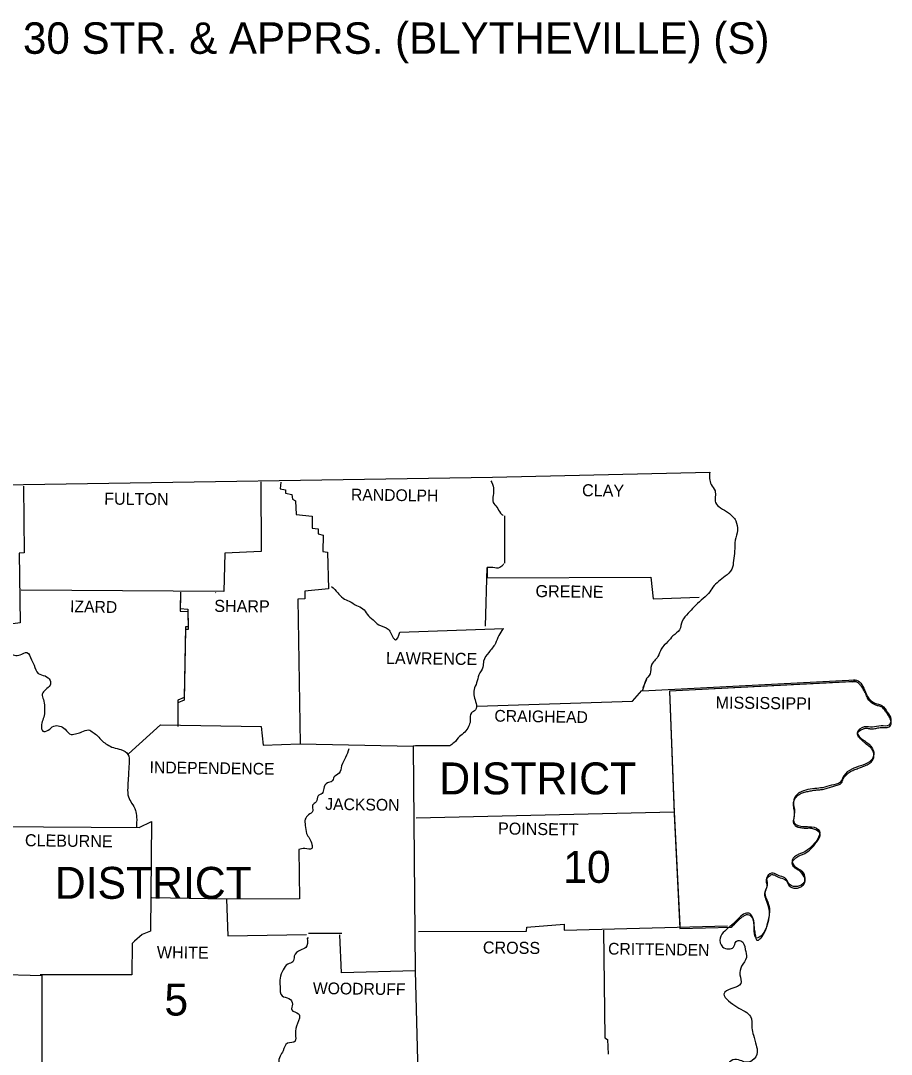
# Model space of a CAD drawing. Extents: x 171 to 3403, y 68 to 2102.
# Drawn here: x 2999.8 to 3303.9, y 1673 to 2034.2 of the extents above; entities that cross this region are included whole.
import ezdxf

# ---------------------------------------------------------------- set-up
doc = ezdxf.new("R2010")
doc.units = 0
for name, color, linetype in [('1', 7, 'Continuous'), ('2', 7, 'Continuous'), ('3', 7, 'Continuous'), ('R_Border', 7, 'Continuous'), ('S_MISC_BOUNDARY', 7, 'Continuous')]:
    doc.layers.add(name, color=color, linetype=linetype)

msp = doc.modelspace()

# ---------------------------------------------------------------- linework, layer by layer
at = {"layer": '1'}
for p, q in [((3216.98, 1800), (3218.15, 1803.62)), ((3217.27, 1801.17), (3218.45, 1804.01)), ((3100.35, 1715.27), (3112, 1715.27))]:
    msp.add_line(p, q, dxfattribs=at)
for points in [[(2703.71, 1871.91), (2861.92, 1871.81), (3000.75, 1872.1), (3164.54, 1874.65), (3240.46, 1876.41)], [(3000.75, 1871.52), (3000.95, 1848.23), (2999.28, 1848.13), (2999.58, 1823.77), (2992.73, 1822.79), (2993.32, 1816.24), (2995.66, 1813.2), (2995.47, 1805.48), (2982.16, 1804.99), (2981.67, 1793.05), (2969.54, 1792.66), (2968.95, 1778.18), (2969.64, 1777), (2969.93, 1753.91), (2990.87, 1752.54), (2990.58, 1700.98), (3007.21, 1700.49), (3007.21, 1648.05), (2994.1, 1647.07), (2993.12, 1635.53), (2971.11, 1635.43)], [(3083.62, 1872.99), (3083.82, 1848.72), (3071.1, 1848.04), (3070.71, 1834.73), (2999.97, 1835.12)], [(3090.67, 1872.89), (3090.37, 1870.54), (3092.33, 1870.25), (3092.23, 1869.07), (3094.48, 1868.58), (3094.68, 1867.02), (3095.75, 1866.33), (3096.05, 1861.64), (3101.63, 1861.05), (3101.63, 1856.84), (3103.68, 1856.55), (3103.68, 1854.88), (3105.44, 1854.4), (3105.34, 1848.72), (3106.91, 1848.43), (3107.3, 1835.61), (3098.98, 1834.83), (3099.08, 1832.09), (3096.54, 1831.99), (3097.42, 1781.5), (3136.85, 1780.62), (3137.53, 1702.16), (3111.8, 1701.47), (3111.31, 1714.68)], [(3168.84, 1861.15), (3168.84, 1844.61)], [(3162.19, 1822.6), (3162.68, 1843.05), (3162.68, 1839.43), (3219.91, 1839.72), (3220.7, 1832.09), (3236.84, 1832.67)], [(3055.64, 1834.44), (3055.44, 1828.76), (3058.18, 1828.57), (3058.28, 1822.3), (3057.3, 1822.3), (3056.91, 1797.65), (3054.66, 1796.67), (3054.66, 1788.45)], [(3055.64, 1833.56), (3055.44, 1827.88), (3058.18, 1827.69), (3058.28, 1821.42), (3057.3, 1821.42), (3056.91, 1796.77), (3054.66, 1795.79), (3054.66, 1787.57)], [(3067.87, 1834.24), (3067.97, 1834.34)], [(3132.25, 1820.44), (3168.55, 1821.72)], [(3216.98, 1800), (3291.24, 1803.81)], [(3159.25, 1794.61), (3213.55, 1796.38), (3216.78, 1800.09)], [(3226.37, 1799.9), (3228.04, 1757.53), (3229.99, 1718.1)], [(3037.44, 1777.98), (3048.6, 1788.06), (3083.82, 1787.57), (3084.5, 1781.02), (3097.32, 1781.5)], [(3149.67, 1780.82), (3137.73, 1780.82), (3136.85, 1780.62)], [(3228.04, 1757.53), (3137.92, 1755.48)], [(2990.87, 1752.54), (3041.16, 1752.25), (3045.46, 1754.3), (3045.17, 1716.05), (3042.24, 1714.78), (3039.59, 1712.53), (3038.71, 1711.65), (3038.62, 1700.69), (3006.62, 1700.69)], [(3096.93, 1744.52), (3097.12, 1727.3), (3071.69, 1727.2), (3045.56, 1727.69)], [(3071.69, 1727.2), (3072.08, 1714.39), (3099.57, 1714.87)], [(3138.71, 1715.85), (3176.47, 1716.05), (3176.57, 1717.42), (3189.68, 1718.4), (3189.68, 1716.34), (3246.63, 1717.91)], [(3203.38, 1716.34), (3203.87, 1678.67), (3204.75, 1678.09), (3205.04, 1673)], [(3100.35, 1713.6), (3099.86, 1713.51)], [(3137.53, 1702.16), (3139, 1648.54), (3115.71, 1648.44), (3115.62, 1646.29), (3108.87, 1645.9), (3108.28, 1634.74), (3100.06, 1634.74)]]:
    msp.add_lwpolyline(points, dxfattribs=at)
for points in [[(3240.46, 1876.41), (3240.95, 1872.1), (3242.32, 1869.85), (3242.52, 1865.75), (3244.18, 1863.98), (3247.02, 1862.22), (3249.56, 1859.39), (3250.15, 1856.06), (3249.36, 1852.63), (3249.17, 1848.82), (3248.78, 1845.49), (3248.19, 1842.46), (3245.84, 1840.01), (3243.59, 1838.25), (3241.54, 1836.2), (3240.07, 1834.04), (3237.53, 1831.7), (3234.98, 1829.25), (3232.93, 1827.1), (3230.87, 1824.36), (3229.89, 1821.33), (3227.64, 1819.17), (3225.88, 1817.22), (3223.53, 1814.57), (3222.36, 1811.93), (3220.11, 1808.9), (3219.62, 1805.96), (3218.15, 1803.62), (3218.06, 1803.22)], [(3164.05, 1873.38), (3164.93, 1870.93), (3164.83, 1868.29), (3164.83, 1865.84), (3166.1, 1864.18), (3167.37, 1862.13), (3168.35, 1861.24)], [(3168.45, 1844.32), (3167.18, 1843.05), (3164.73, 1843.05), (3162.68, 1843.05)], [(3108.38, 1836.49), (3110.53, 1834.24), (3112.39, 1832.38), (3114.54, 1831.31), (3117.08, 1829.84), (3119.33, 1828.66), (3120.8, 1826.8), (3122.86, 1824.75), (3124.91, 1823.09), (3128.14, 1821.52), (3129.22, 1819.86), (3130.68, 1817.8), (3132.25, 1820.44)], [(3168.25, 1821.62), (3166.79, 1819.27), (3165.61, 1816.53), (3163.26, 1813.4), (3161.5, 1810.37), (3161.21, 1808.31), (3159.84, 1805.57), (3159.06, 1802.83), (3158.18, 1800.49), (3158.18, 1798.04), (3158.86, 1795.59), (3158.67, 1793.34), (3157.2, 1792.27), (3156.81, 1789.43), (3156.22, 1787.47), (3154.95, 1785.52), (3153.09, 1784.05), (3151.13, 1781.8), (3149.67, 1780.82)], [(2995.66, 1813.2), (2999.58, 1812.52), (3001.93, 1813.4), (3003.59, 1810.86), (3004.47, 1808.9), (3005.94, 1806.06), (3008.29, 1805.18), (3010.05, 1803.62), (3010.05, 1801.95), (3008.48, 1800.39), (3007.31, 1798.82), (3007.7, 1796.96), (3008.09, 1794.42), (3008.09, 1791.97), (3007.5, 1789.72), (3007.01, 1787.67), (3007.5, 1785.91), (3009.36, 1786.2), (3011.32, 1787.67), (3013.37, 1787.67), (3015.33, 1786.59), (3017.38, 1784.73), (3019.44, 1785.12), (3021.1, 1785.61), (3023.45, 1786.3), (3025.11, 1785.42), (3026.58, 1784.24), (3028.34, 1782.38), (3030.01, 1781.21), (3032.16, 1780.13), (3034.8, 1779.45), (3037.25, 1777.79), (3037.64, 1774.95), (3037.54, 1772.5), (3037.34, 1769.47), (3037.15, 1766.14), (3037.44, 1762.91), (3038.52, 1760.76), (3039.89, 1758.22), (3040.28, 1755.87), (3040.18, 1752.15)], [(3290.16, 1803.71), (3291.24, 1803.81), (3294.57, 1800.29), (3296.03, 1797.35), (3298.19, 1795.69), (3300.63, 1794.81), (3302.49, 1792.56), (3303.76, 1790.11), (3303.08, 1787.96), (3300.34, 1787.77), (3297.31, 1787.28), (3294.37, 1787.37), (3292.02, 1785.42), (3294.18, 1782.78), (3297.01, 1780.33), (3297.8, 1777.69), (3296.23, 1775.14), (3293.1, 1773.77), (3290.07, 1772.6), (3287.33, 1770.25), (3286.05, 1768), (3283.02, 1767.02), (3279.89, 1766.14), (3277.15, 1765.85), (3274.02, 1765.26), (3270.99, 1763.8), (3269.72, 1761.25), (3270.11, 1757.63), (3270.01, 1753.82), (3273.24, 1752.54), (3276.08, 1752.45), (3278.81, 1750.98), (3278.52, 1748.83), (3276.47, 1746.09), (3274.02, 1743.93), (3271.57, 1742.86), (3269.32, 1740.8), (3270.11, 1738.75), (3272.16, 1737.38), (3273.63, 1735.13), (3273.43, 1733.07), (3271.09, 1731.61), (3268.54, 1732.19), (3266.68, 1734.64), (3264.53, 1735.42), (3262.67, 1736.3), (3260.52, 1735.03), (3260.52, 1732.19), (3259.74, 1729.16), (3260.42, 1726.91), (3261.3, 1723.78), (3261.2, 1721.43), (3260.42, 1718.1), (3258.76, 1714.68), (3256.8, 1713.6), (3256.02, 1717.32), (3255.63, 1720.35), (3254.45, 1722.12), (3252.89, 1722.21), (3250.83, 1720.75), (3248.58, 1718.49), (3245.74, 1716.05), (3244.08, 1713.6), (3244.96, 1710.57), (3247.11, 1709.79), (3248.78, 1710.37), (3249.66, 1712.33), (3251.32, 1712.62), (3252.89, 1709.59)], [(3114.44, 1779.74), (3113.27, 1776.71), (3111.9, 1773.77), (3111.02, 1771.23), (3109.16, 1769.76), (3108.57, 1768.39), (3106.91, 1767.81), (3105.64, 1765.85), (3105.05, 1764.09), (3103.68, 1763.31), (3103, 1761.15), (3101.72, 1759.98), (3101.82, 1758.02), (3100.35, 1756.65), (3099.18, 1755.09), (3099.18, 1752.93), (3099.67, 1750.1), (3100.65, 1748.43), (3101.53, 1746.28), (3101.43, 1744.91), (3098.98, 1744.91), (3096.93, 1744.52)], [(3099.86, 1713.51), (3099.37, 1710.28), (3097.52, 1709.4), (3095.36, 1707.24), (3094.87, 1705.29), (3093.11, 1704.5), (3091.45, 1702.45), (3090.37, 1699.61), (3090.37, 1696.68), (3091.06, 1693.35), (3093.5, 1692.47), (3094.68, 1690.51), (3094.48, 1688.46), (3096.83, 1687.09), (3097.22, 1685.91), (3096.83, 1684.64), (3095.75, 1681.02), (3095.85, 1678.58), (3095.66, 1677.5), (3093.02, 1676.81), (3091.45, 1674.17), (3090.37, 1672.31), (3089.98, 1669.87), (3090.28, 1668.11), (3089.49, 1666.74), (3089.2, 1664.68), (3088.22, 1662.92), (3087.34, 1661.26), (3088.32, 1659.3), (3088.03, 1657.93), (3087.44, 1655.78), (3087.93, 1655.09)], [(3252.89, 1709.59), (3253.28, 1706.75), (3251.62, 1703.72), (3251.03, 1700.69), (3251.32, 1697.65), (3248.19, 1695.99), (3245.45, 1694.03), (3247.02, 1691.69), (3249.95, 1689.53), (3252.89, 1687.87), (3254.75, 1686.21), (3255.24, 1682.2), (3255.72, 1679.65), (3256.7, 1676.13), (3257.09, 1673.68), (3255.33, 1670.75), (3253.28, 1670.16), (3251.13, 1670.85), (3248.58, 1671.04), (3246.53, 1669.09), (3245.06, 1666.35), (3243.59, 1663.61), (3242.52, 1661.26), (3241.44, 1658.71), (3239.29, 1655.78), (3236.65, 1655.29), (3233.51, 1654.51), (3231.66, 1652.35), (3231.95, 1648.73), (3233.71, 1646.29), (3235.08, 1643.26), (3236.06, 1640.61), (3235.57, 1637.29), (3234.2, 1634.84), (3232.44, 1633.37), (3231.66, 1630.24), (3230.38, 1627.89), (3229.21, 1627.11), (3226.86, 1627.31), (3224.32, 1627.8), (3222.16, 1627.6), (3220.11, 1626.52), (3218.06, 1627.21), (3215.9, 1629.56), (3214.14, 1631.32), (3212.19, 1632), (3210.13, 1630.93), (3209.74, 1627.7), (3210.72, 1624.37), (3211.6, 1619.87), (3210.72, 1617.13), (3210.42, 1612.63)]]:
    msp.add_spline(points, degree=3, dxfattribs=at)
at = {"layer": 'S_MISC_BOUNDARY'}
for p, q in [((3290.19, 1803.13), (3291.26, 1803.23)), ((3290.35, 1803.15), (3290.19, 1803.13)), ((3291.26, 1803.23), (3290.35, 1803.15))]:
    msp.add_line(p, q, dxfattribs=at)
for points in [[(3291.26, 1803.23), (3226.37, 1799.9), (3228.06, 1756.95), (3230.05, 1716.87), (3247.99, 1717.37)], [(3290.18, 1803.18), (3226.37, 1799.9), (3228.06, 1756.95), (3230.05, 1716.87), (3247.99, 1717.37)], [(3290.19, 1803.13), (3290.18, 1803.18)]]:
    msp.add_lwpolyline(points, dxfattribs=at)
for points in [[(3247.99, 1717.37), (3248.6, 1717.92), (3250.86, 1720.17), (3251.84, 1720.96), (3252.37, 1721.31), (3252.91, 1721.63), (3253.69, 1721.81), (3254.48, 1721.54), (3254.9, 1721.16), (3255.24, 1720.74), (3255.49, 1720.28), (3255.65, 1719.77), (3255.77, 1719.02), (3255.86, 1718.26), (3256.04, 1716.74), (3256.36, 1714.86), (3256.82, 1713.02), (3256.96, 1712.84), (3257.17, 1712.81), (3257.74, 1713.06), (3258.78, 1714.1), (3259.28, 1714.93), (3259.73, 1715.77), (3260.12, 1716.63), (3260.44, 1717.52), (3261.23, 1720.85), (3261.32, 1723.2), (3260.44, 1726.33), (3259.76, 1728.58), (3259.75, 1729.33), (3259.99, 1730.09), (3260.31, 1730.85), (3260.54, 1731.61), (3260.55, 1731.96), (3260.5, 1732.31), (3260.33, 1733.03), (3260.27, 1733.74), (3260.54, 1734.45), (3260.78, 1734.75), (3261.03, 1735.03), (3261.57, 1735.48), (3262.13, 1735.74), (3262.69, 1735.72), (3263.16, 1735.54), (3263.62, 1735.3), (3264.09, 1735.06), (3264.55, 1734.84), (3266.71, 1734.06), (3267.26, 1733.59), (3267.65, 1732.91), (3268.03, 1732.19), (3268.56, 1731.61), (3269.82, 1731.07), (3271.11, 1731.03), (3272.35, 1731.51), (3272.93, 1731.93), (3273.46, 1732.49), (3273.65, 1734.55), (3272.18, 1736.8), (3271.7, 1737.19), (3271.16, 1737.48), (3270.62, 1737.78), (3270.13, 1738.17), (3269.42, 1739.19), (3269.35, 1740.22), (3269.76, 1740.8), (3270.3, 1741.34), (3271.6, 1742.28), (3272.21, 1742.58), (3272.84, 1742.8), (3273.46, 1743.04), (3274.04, 1743.35), (3276.49, 1745.51), (3277.07, 1746.16), (3277.59, 1746.83), (3278.54, 1748.25), (3279.02, 1749.32), (3279.05, 1749.89), (3278.84, 1750.4), (3278.56, 1750.7), (3278.26, 1750.96), (3277.59, 1751.38), (3276.1, 1751.87), (3275.39, 1751.94), (3274.68, 1751.93), (3273.97, 1751.91), (3273.26, 1751.96), (3272.37, 1752.09), (3271.48, 1752.24), (3270.67, 1752.58), (3270.03, 1753.24), (3269.91, 1753.47), (3269.82, 1753.71), (3269.73, 1754.19), (3269.82, 1755.14), (3270.04, 1756.1), (3270.13, 1757.05), (3270.04, 1757.96), (3269.9, 1758.86), (3269.78, 1759.77), (3269.74, 1760.67), (3269.83, 1761.36), (3270.08, 1762.03), (3271.01, 1763.22), (3271.37, 1763.52), (3271.73, 1763.77), (3272.47, 1764.18), (3273.24, 1764.47), (3274.04, 1764.68), (3275.6, 1765.01), (3277.17, 1765.27), (3277.86, 1765.34), (3278.55, 1765.39), (3279.91, 1765.56), (3281.49, 1765.98), (3283.04, 1766.44), (3284.57, 1766.89), (3286.08, 1767.42), (3286.53, 1767.83), (3286.79, 1768.44), (3287.01, 1769.1), (3287.35, 1769.67), (3287.97, 1770.34), (3288.61, 1770.99), (3290.09, 1772.02), (3291.6, 1772.62), (3293.12, 1773.2), (3294.7, 1773.82), (3296.25, 1774.57), (3296.86, 1775.05), (3297.32, 1775.69), (3297.82, 1777.11), (3297.85, 1777.77), (3297.72, 1778.46), (3297.45, 1779.14), (3297.04, 1779.75), (3296.35, 1780.43), (3295.63, 1781.01), (3294.9, 1781.57), (3294.2, 1782.2), (3292.87, 1783.51), (3292.33, 1784.18), (3292.05, 1784.84), (3292.04, 1784.98), (3292.06, 1785.13), (3292.21, 1785.42), (3292.79, 1785.97), (3293.58, 1786.44), (3294.39, 1786.8), (3294.76, 1786.89), (3295.13, 1786.91), (3295.87, 1786.83), (3296.6, 1786.71), (3297.33, 1786.7), (3298.85, 1786.94), (3300.36, 1787.19), (3301.04, 1787.2), (3301.73, 1787.14), (3302.42, 1787.15), (3303.1, 1787.38), (3303.23, 1787.47), (3303.35, 1787.57), (3303.56, 1787.81), (3303.81, 1788.37), (3303.79, 1789.53), (3303.25, 1790.77), (3302.51, 1791.98), (3301.66, 1793.19), (3300.66, 1794.23), (3300.09, 1794.54), (3299.46, 1794.72), (3298.81, 1794.87), (3298.21, 1795.11), (3296.06, 1796.78), (3295.61, 1797.47), (3295.29, 1798.22), (3294.98, 1798.98), (3294.59, 1799.71), (3293.9, 1800.8), (3293.18, 1801.87), (3292.33, 1802.74), (3291.83, 1803.05), (3291.55, 1803.16), (3291.26, 1803.23), (3290.19, 1803.13)], [(3296.38, 1786.74), (3296.6, 1786.71), (3297.33, 1786.7), (3298.85, 1786.94), (3300.36, 1787.19), (3301.04, 1787.2), (3301.73, 1787.14), (3302.42, 1787.15), (3303.1, 1787.38), (3303.23, 1787.47), (3303.35, 1787.57), (3303.56, 1787.81), (3303.81, 1788.37), (3303.79, 1789.53), (3303.25, 1790.77), (3302.51, 1791.98), (3301.66, 1793.19), (3300.66, 1794.23), (3300.09, 1794.54), (3299.46, 1794.72), (3298.81, 1794.87), (3298.21, 1795.11), (3296.06, 1796.78), (3295.61, 1797.47), (3295.29, 1798.22), (3294.98, 1798.98), (3294.59, 1799.71), (3293.9, 1800.8), (3293.18, 1801.87), (3292.33, 1802.74), (3291.83, 1803.05), (3291.55, 1803.16), (3291.26, 1803.23)], [(3286.92, 1768.82), (3287.01, 1769.1), (3287.35, 1769.67), (3287.97, 1770.34), (3288.61, 1770.99), (3290.09, 1772.02), (3291.6, 1772.62), (3293.12, 1773.2), (3294.7, 1773.82), (3296.25, 1774.57), (3296.86, 1775.05), (3297.32, 1775.69), (3297.82, 1777.11), (3297.85, 1777.77), (3297.72, 1778.46), (3297.45, 1779.14), (3297.04, 1779.75), (3296.35, 1780.43), (3295.63, 1781.01), (3294.9, 1781.57), (3294.2, 1782.2), (3292.87, 1783.51), (3292.33, 1784.18), (3292.05, 1784.84), (3292.04, 1784.98), (3292.06, 1785.13), (3292.21, 1785.42), (3292.79, 1785.97), (3293.58, 1786.44), (3294.39, 1786.8), (3294.76, 1786.89), (3295.13, 1786.91), (3295.87, 1786.83), (3296.38, 1786.74)], [(3271.36, 1752.27), (3270.67, 1752.58), (3270.03, 1753.24), (3269.91, 1753.47), (3269.82, 1753.71), (3269.73, 1754.19), (3269.82, 1755.14), (3270.04, 1756.1), (3270.13, 1757.05), (3270.04, 1757.96), (3269.9, 1758.86), (3269.78, 1759.77), (3269.74, 1760.67), (3269.83, 1761.36), (3270.08, 1762.03), (3271.01, 1763.22), (3271.37, 1763.52), (3271.73, 1763.77), (3272.47, 1764.18), (3273.24, 1764.47), (3274.04, 1764.68), (3275.6, 1765.01), (3277.17, 1765.27), (3277.86, 1765.34), (3278.55, 1765.39), (3279.91, 1765.56), (3281.49, 1765.98), (3283.04, 1766.44), (3284.57, 1766.89), (3286.08, 1767.42), (3286.53, 1767.83), (3286.79, 1768.44), (3286.92, 1768.82)], [(3273.44, 1735.03), (3272.18, 1736.8), (3271.7, 1737.19), (3271.16, 1737.48), (3270.62, 1737.78), (3270.13, 1738.17), (3269.42, 1739.19), (3269.35, 1740.22), (3269.76, 1740.8), (3270.3, 1741.34), (3271.6, 1742.28), (3272.21, 1742.58), (3272.84, 1742.8), (3273.46, 1743.04), (3274.04, 1743.35), (3276.49, 1745.51), (3277.07, 1746.16), (3277.59, 1746.83), (3278.54, 1748.25), (3279.02, 1749.32), (3279.05, 1749.89), (3278.84, 1750.4), (3278.56, 1750.7), (3278.26, 1750.96), (3277.59, 1751.38), (3276.1, 1751.87), (3275.39, 1751.94), (3274.68, 1751.93), (3273.97, 1751.91), (3273.26, 1751.96), (3272.37, 1752.09), (3271.48, 1752.24), (3271.36, 1752.27)], [(3261.26, 1723.47), (3260.44, 1726.33), (3259.76, 1728.58), (3259.75, 1729.33), (3259.99, 1730.09), (3260.31, 1730.85), (3260.54, 1731.61), (3260.55, 1731.96), (3260.5, 1732.31), (3260.33, 1733.03), (3260.27, 1733.74), (3260.54, 1734.45), (3260.78, 1734.75), (3261.03, 1735.03), (3261.57, 1735.48), (3262.13, 1735.74), (3262.69, 1735.72), (3263.16, 1735.54), (3263.62, 1735.3), (3264.09, 1735.06), (3264.55, 1734.84), (3266.71, 1734.06), (3267.26, 1733.59), (3267.65, 1732.91), (3268.03, 1732.19), (3268.56, 1731.61), (3269.82, 1731.07), (3271.11, 1731.03), (3272.35, 1731.51), (3272.93, 1731.93), (3273.46, 1732.49), (3273.65, 1734.55), (3273.44, 1735.03)], [(3247.99, 1717.37), (3248.6, 1717.92), (3250.86, 1720.17), (3251.84, 1720.96), (3252.37, 1721.31), (3252.91, 1721.63), (3253.69, 1721.81), (3254.48, 1721.54), (3254.9, 1721.16), (3255.24, 1720.74), (3255.49, 1720.28), (3255.65, 1719.77), (3255.77, 1719.02), (3255.86, 1718.26), (3256.04, 1716.74), (3256.36, 1714.86), (3256.82, 1713.02), (3256.96, 1712.84), (3257.17, 1712.81), (3257.74, 1713.06), (3258.78, 1714.1), (3259.28, 1714.93), (3259.73, 1715.77), (3260.12, 1716.63), (3260.44, 1717.52), (3261.23, 1720.85), (3261.32, 1723.2), (3261.26, 1723.47)]]:
    msp.add_spline(points, degree=3, dxfattribs=at)

# ---------------------------------------------------------------- texts
at = {"layer": '2'}
for s, height, rotation, p in [('CLAY', 4.206, 359.2258, (3195.85, 1868)), ('FULTON', 4.206, 359.4996, (3028.93, 1865.06)), ('RANDOLPH', 4.109, 359.2583, (3115.13, 1866.53)), ('GREENE', 4.207, 359.2361, (3179.6, 1832.77)), ('IZARD', 4.108, 358.9258, (3016.99, 1827.49)), ('SHARP', 4.206, 359.3905, (3067.38, 1827.59)), ('LAWRENCE', 4.207, 359.2678, (3127.36, 1809.39)), ('MISSISSIPPI', 4.2062, 359.3097, (3242.52, 1793.83)), ('CRAIGHEAD', 4.109, 359.1159, (3165.22, 1789.23)), ('INDEPENDENCE', 4.1081, 359.2187, (3044.78, 1771.23)), ('JACKSON', 4.108, 359.1352, (3106.13, 1758.41)), ('POINSETT', 4.206, 359.1987, (3166.49, 1749.8)), ('CLEBURNE', 4.206, 359.2535, (3001.24, 1745.69)), ('CROSS', 4.206, 359.3839, (3161.21, 1708.22)), ('WHITE', 4.207, 359.3139, (3047.32, 1706.56)), ('CRITTENDEN', 4.109, 359.213, (3204.94, 1707.83)), ('WOODRUFF', 4.108, 359.2748, (3101.82, 1694.03))]:
    msp.add_text(s, height=height, rotation=rotation, dxfattribs=at).set_placement(p)
at = {"layer": '3'}
for s, height, p in [('DISTRICT', 11.154, (3146, 1763.8)), ('10', 11.154, (3189.29, 1732.88)), ('DISTRICT', 11.154, (3011.71, 1727.3)), ('5', 11.15, (3049.97, 1686.5))]:
    msp.add_text(s, height=height, dxfattribs=at).set_placement(p)
at = {"layer": 'R_Border'}
msp.add_text('DITCH NO. 30 STR. & APPRS. (BLYTHEVILLE) (S)', height=11, dxfattribs=at).set_placement((2921.32, 2022.61))

doc.saveas('drawing.dxf')
